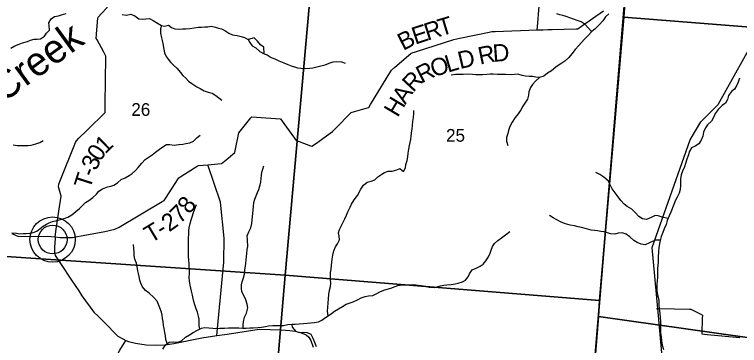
# Model space of a CAD drawing. Extents: x 1715311 to 2083412, y 146837 to 553079.
# Drawn here: x 1908281 to 1920859, y 347369 to 353119 of the extents above; entities that cross this region are included whole.
import ezdxf

# ---------------------------------------------------------------- set-up
doc = ezdxf.new("R2010")
doc.units = 0
for name, color, linetype in [('GM_X_County_Road', 7, 'Continuous'), ('GM_X_Minor_Lake', 7, 'Continuous'), ('GM_X_Minor_River', 7, 'Continuous'), ('GM_X_Minor_River_Text', 7, 'Continuous'), ('GM_X_Section', 7, 'Continuous'), ('GM_X_Section_Text', 7, 'Continuous'), ('GM_X_State_Route', 7, 'Continuous'), ('GM_X_Township', 7, 'Continuous'), ('GM_X_Township_Road', 7, 'Continuous'), ('GM_X_Township_Road_Text', 7, 'Continuous'), ('GM_X_Township_ROW', 7, 'Continuous'), ('GM_X_Unincorporated', 7, 'Continuous'), ('GM_X_Unincorporated_Location', 7, 'Continuous')]:
    doc.layers.add(name, color=color, linetype=linetype)

msp = doc.modelspace()

# ---------------------------------------------------------------- linework, layer by layer
at = {"layer": 'GM_X_County_Road'}
msp.add_lwpolyline([(1908233, 349316), (1908350, 349265), (1908853, 349268), (1908984, 349254), (1908989, 349230), (1908974, 349076), (1908976, 348992), (1908988, 348930), (1909077, 348792), (1909272, 348506), (1909396, 348318), (1909447, 348234), (1909657, 347947), (1909731, 347876), (1909832, 347779), (1910072, 347532), (1910161, 347483), (1910215, 347459), (1910257, 347441), (1910381, 347409), (1910566, 347381), (1910729, 347376), (1910897, 347379), (1911046, 347406), (1911530, 347500), (1911792, 347545), (1911968, 347565), (1912527, 347654), (1912908, 347639), (1913057, 347631), (1913153, 347620), (1913243, 347596), (1913342, 347556), (1913389, 347515), (1913423, 347455), (1913461, 347339)], dxfattribs=at)
at = {"layer": 'GM_X_Minor_Lake'}
for points in [[(1912610, 352437), (1912604, 352549), (1912549, 352589), (1912495, 352654), (1912441, 352716), (1912335, 352686)], [(1912335, 352686), (1912365, 352634), (1912405, 352576), (1912468, 352540), (1912536, 352477), (1912610, 352437)]]:
    msp.add_lwpolyline(points, dxfattribs=at)
at = {"layer": 'GM_X_Minor_River'}
for points in [[(1908220, 352533), (1908288, 352573), (1908364, 352601), (1908422, 352625), (1908504, 352652), (1908560, 352672), (1908622, 352688), (1908674, 352688), (1908730, 352694), (1908800, 352741), (1908834, 352793), (1908888, 352847), (1908881, 352925), (1908877, 352975), (1908915, 353045), (1908977, 353083), (1909045, 353097), (1909097, 353113), (1909177, 353134)], [(1910148, 353121), (1910225, 353108), (1910297, 353122), (1910367, 353094), (1910437, 353043), (1910499, 353037), (1910557, 353043), (1910625, 353047), (1910689, 353014), (1910760, 352966), (1910830, 352928), (1910882, 352918), (1910950, 352933), (1911006, 352893), (1911063, 352867), (1911143, 352865), (1911197, 352868), (1911255, 352872), (1911321, 352878), (1911399, 352890), (1911471, 352899), (1911525, 352899), (1911585, 352905), (1911637, 352907), (1911695, 352915), (1911767, 352898), (1911819, 352882), (1911872, 352870), (1911932, 352842), (1912000, 352793), (1912066, 352765), (1912144, 352755), (1912214, 352737), (1912269, 352720), (1912335, 352686), (1912365, 352634), (1912405, 352576), (1912468, 352540), (1912536, 352477), (1912610, 352437), (1912666, 352419), (1912735, 352372), (1912795, 352346), (1912867, 352316), (1912953, 352282), (1913023, 352253), (1913080, 352227), (1913136, 352209), (1913190, 352195), (1913246, 352186), (1913310, 352180), (1913402, 352184), (1913454, 352190), (1913524, 352209), (1913596, 352227), (1913670, 352247), (1913742, 352273), (1913810, 352294), (1913876, 352302), (1913952, 352294), (1914017, 352272)], [(1918593, 353129), (1918535, 353078), (1918486, 353008), (1918424, 352942), (1918356, 352868), (1918296, 352826), (1918226, 352750), (1918162, 352685), (1918073, 352581), (1918009, 352511), (1917949, 352433), (1917897, 352373), (1917829, 352310), (1917779, 352274), (1917728, 352242), (1917672, 352202), (1917598, 352140), (1917528, 352099), (1917462, 352047), (1917392, 352025), (1917324, 352033), (1917270, 352039), (1917208, 352042), (1917147, 352048), (1917089, 352060), (1917015, 352080), (1916953, 352075), (1916891, 352073), (1916805, 352075), (1916713, 352074), (1916659, 352074), (1916585, 352080), (1916531, 352080), (1916477, 352076), (1916400, 352071), (1916342, 352073), (1916284, 352073), (1916226, 352077), (1916150, 352080), (1916064, 352078), (1916010, 352078), (1915934, 352078), (1915856, 352067)], [(1918292, 352822), (1918238, 352880), (1918182, 352945), (1918113, 352989), (1918043, 353017), (1917917, 353060), (1917849, 353086), (1917794, 353104), (1917740, 353115), (1917688, 353131)], [(1910830, 352928), (1910816, 352868), (1910814, 352794), (1910833, 352716), (1910843, 352666), (1910861, 352586), (1910872, 352511), (1910886, 352455), (1910912, 352391), (1910946, 352341), (1910985, 352291), (1911041, 352241), (1911095, 352188), (1911161, 352112), (1911200, 352062), (1911254, 352014), (1911302, 351963), (1911358, 351919), (1911443, 351863), (1911501, 351835), (1911573, 351794), (1911641, 351768), (1911711, 351754), (1911776, 351714), (1911828, 351673), (1911880, 351631)], [(1917392, 352025), (1917320, 351959), (1917266, 351901), (1917232, 351848), (1917205, 351774), (1917197, 351720), (1917179, 351646), (1917133, 351580), (1917099, 351526), (1917064, 351460), (1917020, 351394), (1916968, 351328), (1916916, 351248), (1916872, 351174), (1916849, 351104), (1916837, 351052), (1916817, 350982), (1916817, 350918), (1916842, 350846)], [(1920860, 352012), (1920835, 351946), (1920815, 351890), (1920773, 351822), (1920721, 351780), (1920669, 351712), (1920648, 351643), (1920614, 351579), (1920558, 351537), (1920488, 351469)], [(1913721, 347884), (1913714, 347966), (1913718, 348036), (1913720, 348102), (1913729, 348178), (1913735, 348258), (1913745, 348330), (1913761, 348394), (1913770, 348450), (1913766, 348518), (1913764, 348584), (1913766, 348638), (1913772, 348692), (1913783, 348762), (1913787, 348818), (1913793, 348870), (1913801, 348938), (1913820, 349014), (1913852, 349084), (1913884, 349136), (1913922, 349204), (1913912, 349270), (1913903, 349324), (1913917, 349386), (1913949, 349444), (1914011, 349568), (1914040, 349634), (1914064, 349692), (1914102, 349770), (1914126, 349826), (1914172, 349897), (1914229, 349973), (1914289, 350085), (1914333, 350157), (1914399, 350205), (1914469, 350225), (1914531, 350248), (1914583, 350298), (1914651, 350348), (1914703, 350372), (1914766, 350398), (1914835, 350399), (1914913, 350419), (1914965, 350441), (1915031, 350389), (1915067, 350455), (1915072, 350511), (1915092, 350585), (1915104, 350647), (1915112, 350711), (1915120, 350781), (1915135, 350843), (1915147, 350895), (1915157, 350947), (1915165, 351005), (1915169, 351059), (1915180, 351131), (1915186, 351189), (1915194, 351261), (1915202, 351331), (1915209, 351399), (1915209, 351451)], [(1920488, 351469), (1920438, 351399), (1920414, 351343), (1920373, 351267), (1920303, 351200), (1920271, 351148), (1920233, 351074), (1920221, 351006), (1920194, 350936), (1920154, 350870), (1920092, 350830), (1920024, 350800), (1919988, 350736), (1919972, 350682), (1919948, 350608), (1919921, 350528), (1919903, 350475), (1919871, 350397), (1919849, 350331), (1919834, 350259), (1919838, 350207), (1919838, 350149), (1919830, 350077), (1919810, 350013), (1919777, 349947), (1919751, 349891), (1919719, 349817), (1919667, 349687), (1919636, 349619), (1919606, 349543), (1919584, 349471), (1919554, 349393), (1919527, 349331), (1919501, 349261), (1919481, 349193), (1919473, 349139), (1919462, 349065), (1919456, 349007), (1919448, 348899), (1919446, 348821), (1919441, 348759), (1919439, 348709), (1919439, 348631), (1919437, 348553), (1919424, 348433), (1919424, 348379), (1919426, 348325), (1919430, 348275), (1919449, 348209), (1919459, 348153), (1919461, 348077), (1919467, 348009), (1919474, 347928), (1919480, 347856), (1919486, 347786), (1919487, 347708), (1919489, 347634), (1919489, 347584), (1919497, 347520), (1919508, 347452), (1919520, 347374), (1919540, 347300)], [(1908236, 349325), (1908316, 349321), (1908376, 349311), (1908430, 349312), (1908486, 349316), (1908546, 349322), (1908606, 349334), (1908666, 349354), (1908728, 349403), (1908780, 349443), (1908834, 349475), (1908884, 349499), (1908940, 349521), (1909016, 349538), (1909082, 349556), (1909140, 349576), (1909206, 349596), (1909278, 349638), (1909346, 349697), (1909410, 349749), (1909462, 349799), (1909512, 349853), (1909570, 349887), (1909638, 349938), (1909701, 349996), (1909747, 350048), (1909809, 350090), (1909895, 350126), (1909953, 350139), (1910005, 350157), (1910067, 350197), (1910131, 350255), (1910201, 350284), (1910273, 350320), (1910325, 350356), (1910383, 350410), (1910425, 350462), (1910488, 350536), (1910548, 350599), (1910616, 350647), (1910668, 350681), (1910730, 350725), (1910796, 350779), (1910854, 350822), (1910918, 350858), (1910978, 350858), (1911052, 350848), (1911132, 350859), (1911200, 350869), (1911252, 350877), (1911322, 350889), (1911388, 350918), (1911450, 350982), (1911502, 351022)], [(1908256, 350852), (1908326, 350842), (1908381, 350842), (1908447, 350845), (1908517, 350845), (1908571, 350851), (1908651, 350871), (1908719, 350898), (1908779, 350930)], [(1912247, 347670), (1912247, 347731), (1912255, 347783), (1912271, 347861), (1912304, 347931), (1912330, 348021), (1912316, 348089), (1912296, 348165), (1912225, 348306), (1912217, 348360), (1912221, 348424), (1912232, 348478), (1912256, 348544), (1912270, 348610), (1912280, 348684), (1912291, 348746), (1912297, 348802), (1912303, 348860), (1912305, 348916), (1912311, 348966), (1912320, 349036), (1912332, 349088), (1912324, 349204), (1912319, 349276), (1912347, 349342), (1912383, 349412), (1912401, 349488), (1912407, 349552), (1912410, 349602), (1912414, 349670), (1912420, 349720), (1912426, 349786), (1912435, 349852), (1912449, 349910), (1912475, 349970), (1912497, 350026), (1912521, 350078), (1912544, 350160), (1912552, 350212), (1912558, 350270), (1912566, 350328), (1912574, 350382), (1912588, 350434), (1912607, 350492)], [(1919618, 349573), (1919520, 349601), (1919449, 349624), (1919395, 349626), (1919327, 349592), (1919247, 349558), (1919175, 349569), (1919113, 349611), (1919049, 349679), (1918990, 349737), (1918912, 349782), (1918858, 349822), (1918802, 349888), (1918755, 349950), (1918699, 350023), (1918651, 350091), (1918616, 350161), (1918578, 350227), (1918506, 350294), (1918435, 350342), (1918369, 350374)], [(1911495, 347654), (1911484, 347712), (1911486, 347764), (1911484, 347824), (1911476, 347876), (1911457, 347950), (1911435, 348004), (1911409, 348073), (1911395, 348133), (1911382, 348185), (1911372, 348243), (1911354, 348311), (1911340, 348365), (1911331, 348419), (1911319, 348489), (1911313, 348559), (1911317, 348615), (1911316, 348665), (1911314, 348723), (1911310, 348787), (1911304, 348859), (1911300, 348912), (1911299, 348976), (1911299, 349170), (1911302, 349234), (1911306, 349306), (1911308, 349362), (1911314, 349416), (1911329, 349490), (1911345, 349550), (1911361, 349604), (1911389, 349680), (1911411, 349746), (1911440, 349820)], [(1919483, 349199), (1919409, 349200), (1919345, 349176), (1919295, 349150), (1919221, 349118), (1919151, 349132), (1919081, 349161), (1919025, 349191), (1918954, 349259), (1918890, 349302), (1918824, 349326), (1918756, 349318), (1918696, 349306), (1918622, 349311), (1918569, 349325), (1918513, 349341), (1918455, 349349), (1918395, 349363), (1918343, 349368), (1918285, 349374), (1918207, 349396), (1918116, 349419), (1918058, 349431), (1917994, 349447), (1917922, 349461), (1917842, 349484), (1917766, 349512), (1917689, 349550), (1917627, 349586), (1917561, 349629)], [(1914746, 348346), (1914808, 348368), (1914884, 348392), (1914934, 348412), (1915012, 348425), (1915076, 348423), (1915142, 348423), (1915210, 348427), (1915283, 348418), (1915339, 348412), (1915407, 348400), (1915477, 348380), (1915561, 348375), (1915613, 348387), (1915669, 348403), (1915727, 348415), (1915779, 348421), (1915857, 348430), (1915925, 348438), (1915981, 348450), (1916051, 348476), (1916103, 348507), (1916149, 348563), (1916173, 348617), (1916221, 348685), (1916289, 348715), (1916359, 348747), (1916409, 348782), (1916460, 348838), (1916502, 348910), (1916532, 348972), (1916548, 349024), (1916576, 349088), (1916606, 349142), (1916665, 349196), (1916729, 349238), (1916797, 349291), (1916873, 349347)], [(1910932, 347403), (1910906, 347476), (1910898, 347540), (1910890, 347594), (1910878, 347662), (1910869, 347718), (1910859, 347786), (1910851, 347837), (1910843, 347895), (1910830, 347949), (1910804, 348023), (1910782, 348081), (1910754, 348139), (1910693, 348209), (1910617, 348276), (1910553, 348322), (1910500, 348386), (1910472, 348454), (1910458, 348504), (1910442, 348566), (1910431, 348619), (1910419, 348669), (1910409, 348743), (1910399, 348799), (1910370, 348869), (1910358, 348931), (1910356, 348989), (1910354, 349057), (1910343, 349121)], [(1910853, 347308), (1910899, 347380), (1910967, 347428), (1911041, 347434), (1911117, 347425), (1911179, 347453), (1911247, 347517), (1911317, 347553), (1911382, 347596), (1911454, 347634), (1911524, 347668), (1911576, 347680), (1911651, 347679), (1911723, 347671), (1911775, 347667), (1911845, 347671), (1911923, 347670), (1911993, 347674), (1912049, 347676), (1912103, 347678), (1912173, 347678), (1912235, 347669), (1912303, 347671), (1912363, 347675), (1912420, 347677), (1912504, 347680), (1912564, 347686), (1912634, 347702), (1912686, 347710), (1912764, 347719), (1912822, 347717), (1912874, 347717), (1912948, 347719), (1913022, 347734), (1913096, 347738), (1913152, 347740), (1913220, 347744), (1913296, 347751), (1913360, 347755), (1913417, 347765), (1913487, 347771), (1913557, 347782), (1913611, 347808), (1913661, 347842), (1913722, 347884), (1913778, 347928), (1913834, 347966), (1913900, 348007), (1913970, 348049), (1914038, 348085), (1914088, 348105), (1914156, 348130), (1914232, 348162), (1914296, 348196), (1914362, 348222), (1914424, 348230), (1914500, 348235), (1914566, 348273), (1914620, 348303), (1914690, 348329), (1914746, 348346)], [(1913085, 347738), (1913104, 347682), (1913159, 347620), (1913227, 347596), (1913289, 347599), (1913359, 347597), (1913423, 347565), (1913456, 347495), (1913484, 347427), (1913516, 347352)]]:
    msp.add_lwpolyline(points, dxfattribs=at)
at = {"layer": 'GM_X_Section'}
for points in [[(1919300, 358705), (1924867, 358127), (1924854, 352597), (1918852, 353071), (1918887, 353573)], [(1913462, 354034), (1912974, 348592), (1907523, 348954), (1907976, 354545)], [(1918887, 353573), (1918852, 353071), (1918430, 348149), (1912974, 348592), (1913462, 354034)], [(1924854, 352597), (1924471, 347017), (1918410, 347873), (1918430, 348149), (1918852, 353071)], [(1907523, 348954), (1912974, 348592), (1912507, 343127), (1907496, 343547), (1907064, 343582)], [(1912974, 348592), (1918430, 348149), (1918410, 347873), (1917995, 342712), (1912785, 343098), (1912507, 343127)], [(1918410, 347873), (1924471, 347017), (1924063, 342119), (1923343, 342193), (1917995, 342712)]]:
    msp.add_lwpolyline(points, close=True, dxfattribs=at)
at = {"layer": 'GM_X_State_Route'}
msp.add_lwpolyline([(1919517, 347180), (1919441, 348011), (1919344, 349069), (1920003, 350939), (1920190, 351257), (1920490, 351556), (1921209, 352852)], dxfattribs=at)
at = {"layer": 'GM_X_Township'}
for points in [[(1919699, 363864), (1919439, 360580), (1918984, 354830), (1918872, 353414), (1918282, 346303), (1917981, 342685), (1915843, 342855), (1912506, 343119), (1908092, 343486), (1907016, 343561), (1905609, 343672), (1902260, 343934), (1900188, 344104), (1897396, 344334), (1896407, 344385)], [(1938948, 340681), (1938232, 340744), (1933753, 341150), (1932944, 341230), (1928821, 341629), (1928217, 341682), (1925166, 341982), (1924036, 342101), (1919669, 342538), (1917981, 342685), (1918282, 346303), (1918872, 353414), (1918984, 354830), (1919439, 360580), (1919699, 363864)]]:
    msp.add_lwpolyline(points, dxfattribs=at)
at = {"layer": 'GM_X_Township_Road'}
for points in [[(1917350, 352853), (1917355, 352904), (1917386, 353266)], [(1908984, 349254), (1909074, 349244), (1909290, 349245), (1909377, 349263), (1909504, 349283), (1909849, 349352), (1910024, 349392), (1910097, 349423), (1910841, 349869), (1910878, 349889), (1910912, 349941), (1911111, 350248), (1911134, 350284), (1911186, 350316), (1911452, 350482), (1911473, 350495), (1911552, 350502), (1911634, 350509), (1911864, 350530), (1911873, 350531), (1911947, 350591), (1912068, 350690), (1912104, 350719), (1912115, 350777), (1912165, 351033), (1912172, 351066), (1912217, 351120), (1912383, 351322), (1912400, 351343), (1912477, 351338), (1912893, 351309), (1912895, 351309), (1912955, 351226), (1913139, 350972), (1913167, 350932), (1913219, 350913), (1913415, 350840), (1913442, 350830), (1913503, 350874), (1913800, 351087), (1913800, 351086), (1913873, 351161), (1914093, 351385), (1914123, 351415), (1914182, 351432), (1914382, 351491), (1914427, 351504), (1914457, 351553), (1914809, 352133), (1914822, 352153), (1914882, 352206), (1915159, 352444), (1915164, 352448), (1915258, 352478), (1915904, 352685), (1915905, 352685), (1916006, 352706), (1916517, 352814), (1916562, 352823), (1916620, 352826), (1917350, 352853), (1917452, 352853), (1917536, 352860), (1917611, 352861), (1918028, 352869), (1918054, 352870), (1918119, 352915), (1918497, 353180)], [(1909857, 351569), (1909868, 352377), (1909868, 352396), (1909831, 352464), (1909715, 352677), (1909700, 352704), (1909706, 352770), (1909706, 352778)], [(1909551, 351119), (1909848, 351410), (1909854, 351417), (1909856, 351504), (1909856, 351553), (1909857, 351569)], [(1908984, 349254), (1909003, 349391), (1909051, 349705), (1909092, 349966), (1909043, 350125), (1909051, 350170), (1909070, 350218), (1909341, 350893), (1909354, 350926), (1909398, 350969), (1909536, 351105), (1909551, 351119)], [(1919420, 348012), (1919441, 348011), (1919472, 348011), (1919989, 348001), (1920013, 348001), (1920084, 347965), (1920176, 347918), (1920216, 347898), (1920214, 347840), (1920204, 347581), (1920204, 347571), (1920297, 347563), (1920863, 347510)]]:
    msp.add_lwpolyline(points, dxfattribs=at)
at = {"layer": 'GM_X_Township_ROW'}
for points in [[(1909706, 352778), (1909729, 353060), (1909730, 353073), (1909788, 353134), (1909887, 353240), (1909890, 353244), (1909884, 353336), (1909862, 353626), (1909858, 353675)], [(1911792, 347545), (1911910, 348818), (1911920, 349232), (1911857, 349858), (1911634, 350509)], [(1908310, 344290), (1908296, 344500), (1908332, 344824), (1908428, 345065), (1908692, 345473), (1908812, 345893), (1908956, 346277), (1909064, 346565), (1909172, 346721), (1909364, 346805), (1909652, 346805), (1909880, 346877), (1910001, 347081), (1910109, 347286), (1910215, 347459)]]:
    msp.add_lwpolyline(points, dxfattribs=at)
at = {"layer": 'GM_X_Unincorporated'}
for radius in [393, 249]:
    msp.add_circle((1908943, 349210), radius, dxfattribs=at)
at = {"layer": 'GM_X_Unincorporated_Location'}
msp.add_line((1908943, 349210), (1908943, 349210), dxfattribs=at)

# ---------------------------------------------------------------- texts
at = {"layer": 'GM_X_Minor_River_Text'}
msp.add_text('Creek', height=500, rotation=36.0028, dxfattribs=at).set_placement((1908079, 351574))
at = {"layer": 'GM_X_Section_Text'}
for s, p in [('26', (1910308, 351358)), ('25', (1915768, 350909))]:
    msp.add_text(s, height=221, rotation=0, dxfattribs=at).set_placement(p)
at = {"layer": 'GM_X_Township_Road_Text'}
for s, rotation, p in [('T', 16.8396, (1915678, 352738)), ('E', 18.2018, (1915232, 352593)), ('R', 17.8141, (1915444, 352663)), ('B', 27.1079, (1915024, 352486)), ('R', 11.6283, (1916356, 352248)), ('D', 4.0833, (1916587, 352296)), ('D', 13.2049, (1916011, 352170)), ('O', 18.0018, (1915551, 352026)), ('L', 16.6254, (1915800, 352107)), ('R', 26.9525, (1915343, 351919)), ('R', 47.0565, (1915197, 351755)), ('A', 57.3617, (1915063, 351544)), ('H', 59.0925, (1914929, 351319)), ('1', 44.1819, (1909856, 350687)), ('0', 55.9098, (1909764, 350548)), ('3', 68.1979, (1909704, 350393)), ('-', 68.1977, (1909659, 350279)), ('T', 72.2182, (1909592, 350071)), ('8', 52.8019, (1911318, 349638)), ('7', 44.1201, (1911153, 349472)), ('2', 35.4384, (1910964, 349333)), ('T', 31.0975, (1910646, 349140)), ('-', 31.0975, (1910838, 349256))]:
    msp.add_text(s, height=300, rotation=rotation, dxfattribs=at).set_placement(p)

doc.saveas('drawing.dxf')
